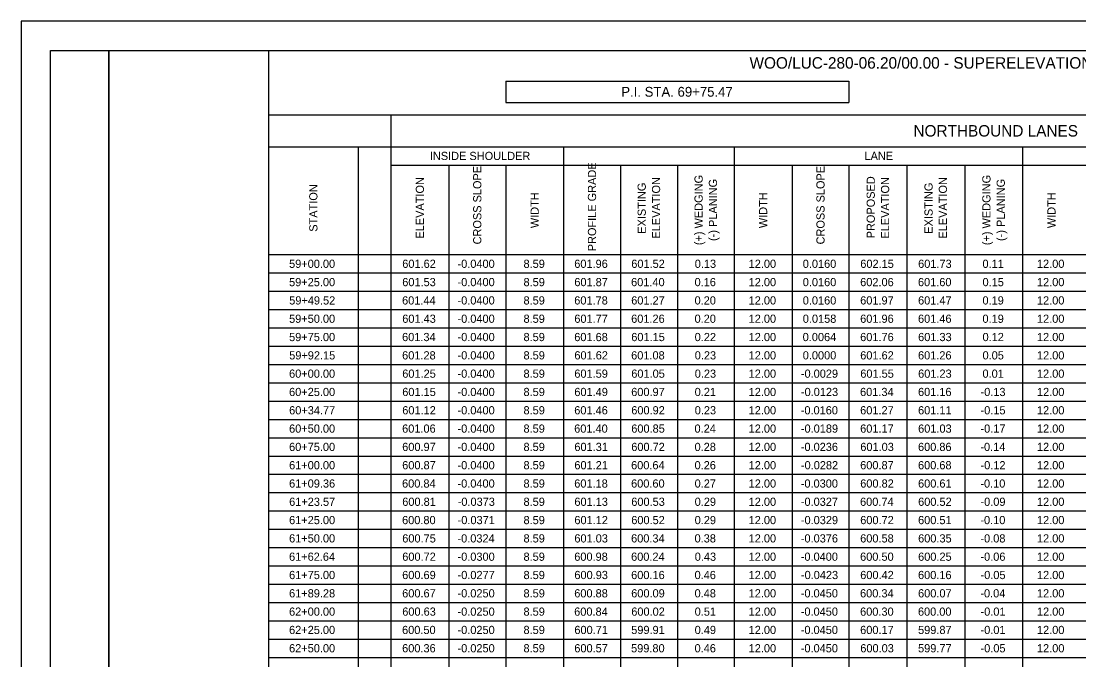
# Model space of a CAD drawing. Extents: x 0 to 34, y 0 to 22.
# Drawn here: x 0 to 18.07, y 11.08 to 22 of the extents above; entities that cross this region are included whole.
import ezdxf

# ---------------------------------------------------------------- set-up
doc = ezdxf.new("R2010")
doc.units = 0
for name, color, linetype in [('SH_Border', 7, 'Continuous'), ('SH_Cut_Line', 7, 'Continuous'), ('SH_Text', 7, 'Continuous')]:
    doc.layers.add(name, color=color, linetype=linetype)

msp = doc.modelspace()

# ---------------------------------------------------------------- linework, layer by layer
at = {"layer": 'SH_Border'}
for points in [[(0.5, 21.5), (1.5, 21.5), (1.5, 0.5), (0.5, 0.5)], [(1.5, 21.5), (33.5, 21.5), (33.5, 0.5), (1.5, 0.5)]]:
    msp.add_lwpolyline(points, close=True, dxfattribs=at)
at = {"layer": 'SH_Cut_Line'}
msp.add_lwpolyline([(0, 0), (34, 0), (34, 22), (0, 22)], close=True, dxfattribs=at)
at = {"layer": 'SH_Text'}
for p, q in [((4.225, 21.5), (29.277, 21.5)), ((4.225, 21.5), (4.225, 0.484)), ((8.277, 20.973), (14.14, 20.973)), ((8.277, 20.973), (8.277, 20.611)), ((14.14, 20.973), (14.14, 20.611)), ((8.277, 20.611), (14.14, 20.611)), ((4.225, 20.396), (29.277, 20.396)), ((6.317, 20.396), (6.317, 0.484)), ((4.225, 19.853), (29.277, 19.853)), ((5.757, 19.853), (5.757, 0.484)), ((9.265, 19.853), (9.265, 0.484)), ((12.18, 19.853), (12.18, 0.484)), ((17.105, 19.853), (17.105, 0.484)), ((6.317, 19.54), (26.954, 19.54)), ((7.305, 19.54), (7.305, 0.484)), ((8.277, 19.54), (8.277, 0.484)), ((10.237, 19.54), (10.237, 0.484)), ((11.209, 19.54), (11.209, 0.484)), ((13.169, 19.54), (13.169, 0.484)), ((14.14, 19.54), (14.14, 0.484)), ((15.129, 19.54), (15.129, 0.484)), ((16.117, 19.54), (16.117, 0.484)), ((4.225, 18.008), (29.277, 18.008)), ((4.225, 17.695), (29.277, 17.695)), ((4.225, 17.382), (29.277, 17.382)), ((4.225, 17.069), (29.277, 17.069)), ((4.225, 16.756), (29.277, 16.756)), ((4.225, 16.444), (29.277, 16.444)), ((4.225, 16.131), (29.277, 16.131)), ((4.225, 15.818), (29.277, 15.818)), ((4.225, 15.505), (29.277, 15.505)), ((4.225, 15.192), (29.277, 15.192)), ((4.225, 14.879), (29.277, 14.879)), ((4.225, 14.566), (29.277, 14.566)), ((4.225, 14.253), (29.277, 14.253)), ((4.225, 13.94), (29.277, 13.94)), ((4.225, 13.627), (29.277, 13.627)), ((4.225, 13.314), (29.277, 13.314)), ((4.225, 13.001), (29.277, 13.001)), ((4.225, 12.688), (29.277, 12.688)), ((4.225, 12.375), (29.277, 12.375)), ((4.225, 12.062), (29.277, 12.062)), ((4.225, 11.749), (29.277, 11.749)), ((4.225, 11.436), (29.277, 11.436)), ((4.225, 11.124), (29.277, 11.124))]:
    msp.add_line(p, q, dxfattribs=at)

# ---------------------------------------------------------------- texts
for s, height, p in [('WOO/LUC-280-06.20/00.00 - SUPERELEVATION TABLE', 0.196, (12.442, 21.188)), ('P.I. STA. 69+75.47', 0.168, (10.251, 20.708)), ('NORTHBOUND LANES', 0.196, (15.242, 20.027)), ('INSIDE SHOULDER', 0.14, (6.981, 19.626)), ('LANE', 0.14, (14.406, 19.626)), ('59+00.00', 0.14, (4.577, 17.782)), ('601.62', 0.14, (6.51, 17.782)), ('-0.0400', 0.14, (7.454, 17.782)), ('8.59', 0.14, (8.581, 17.782)), ('601.96', 0.14, (9.448, 17.782)), ('601.52', 0.14, (10.422, 17.782)), ('0.13', 0.14, (11.506, 17.782)), ('12.00', 0.14, (12.427, 17.782)), ('0.0160', 0.14, (13.351, 17.782)), ('602.15', 0.14, (14.334, 17.782)), ('601.73', 0.14, (15.322, 17.782)), ('0.11', 0.14, (16.421, 17.782)), ('12.00', 0.14, (17.352, 17.782)), ('59+25.00', 0.14, (4.577, 17.469)), ('601.53', 0.14, (6.51, 17.469)), ('-0.0400', 0.14, (7.454, 17.469)), ('8.59', 0.14, (8.581, 17.469)), ('601.87', 0.14, (9.449, 17.469)), ('601.40', 0.14, (10.419, 17.469)), ('0.16', 0.14, (11.503, 17.469)), ('12.00', 0.14, (12.427, 17.469)), ('0.0160', 0.14, (13.351, 17.469)), ('602.06', 0.14, (14.332, 17.469)), ('601.60', 0.14, (15.319, 17.469)), ('0.15', 0.14, (16.422, 17.469)), ('12.00', 0.14, (17.352, 17.469)), ('59+49.52', 0.14, (4.579, 17.156)), ('601.44', 0.14, (6.507, 17.156)), ('-0.0400', 0.14, (7.454, 17.156)), ('8.59', 0.14, (8.581, 17.156)), ('601.78', 0.14, (9.448, 17.156)), ('601.27', 0.14, (10.421, 17.156)), ('0.20', 0.14, (11.503, 17.156)), ('12.00', 0.14, (12.427, 17.156)), ('0.0160', 0.14, (13.351, 17.156)), ('601.97', 0.14, (14.332, 17.156)), ('601.47', 0.14, (15.321, 17.156)), ('0.19', 0.14, (16.421, 17.156)), ('12.00', 0.14, (17.352, 17.156)), ('59+50.00', 0.14, (4.577, 16.843)), ('601.43', 0.14, (6.51, 16.843)), ('-0.0400', 0.14, (7.454, 16.843)), ('8.59', 0.14, (8.581, 16.843)), ('601.77', 0.14, (9.449, 16.843)), ('601.26', 0.14, (10.42, 16.843)), ('0.20', 0.14, (11.503, 16.843)), ('12.00', 0.14, (12.427, 16.843)), ('0.0158', 0.14, (13.352, 16.843)), ('601.96', 0.14, (14.332, 16.843)), ('601.46', 0.14, (15.32, 16.843)), ('0.19', 0.14, (16.421, 16.843)), ('12.00', 0.14, (17.352, 16.843)), ('59+75.00', 0.14, (4.577, 16.53)), ('601.34', 0.14, (6.507, 16.53)), ('-0.0400', 0.14, (7.454, 16.53)), ('8.59', 0.14, (8.581, 16.53)), ('601.68', 0.14, (9.448, 16.53)), ('601.15', 0.14, (10.422, 16.53)), ('0.22', 0.14, (11.505, 16.53)), ('12.00', 0.14, (12.427, 16.53)), ('0.0064', 0.14, (13.35, 16.53)), ('601.76', 0.14, (14.332, 16.53)), ('601.33', 0.14, (15.322, 16.53)), ('0.12', 0.14, (16.422, 16.53)), ('12.00', 0.14, (17.352, 16.53)), ('59+92.15', 0.14, (4.579, 16.217)), ('601.28', 0.14, (6.508, 16.217)), ('-0.0400', 0.14, (7.454, 16.217)), ('8.59', 0.14, (8.581, 16.217)), ('601.62', 0.14, (9.45, 16.217)), ('601.08', 0.14, (10.42, 16.217)), ('0.23', 0.14, (11.506, 16.217)), ('12.00', 0.14, (12.427, 16.217)), ('0.0000', 0.14, (13.351, 16.217)), ('601.62', 0.14, (14.333, 16.217)), ('601.26', 0.14, (15.32, 16.217)), ('0.05', 0.14, (16.422, 16.217)), ('12.00', 0.14, (17.352, 16.217)), ('60+00.00', 0.14, (4.577, 15.904)), ('601.25', 0.14, (6.51, 15.904)), ('-0.0400', 0.14, (7.454, 15.904)), ('8.59', 0.14, (8.581, 15.904)), ('601.59', 0.14, (9.449, 15.904)), ('601.05', 0.14, (10.422, 15.904)), ('0.23', 0.14, (11.506, 15.904)), ('12.00', 0.14, (12.427, 15.904)), ('-0.0029', 0.14, (13.319, 15.904)), ('601.55', 0.14, (14.334, 15.904)), ('601.23', 0.14, (15.322, 15.904)), ('0.01', 0.14, (16.421, 15.904)), ('12.00', 0.14, (17.352, 15.904)), ('60+25.00', 0.14, (4.577, 15.591)), ('601.15', 0.14, (6.51, 15.591)), ('-0.0400', 0.14, (7.454, 15.591)), ('8.59', 0.14, (8.581, 15.591)), ('601.49', 0.14, (9.449, 15.591)), ('600.97', 0.14, (10.421, 15.591)), ('0.21', 0.14, (11.505, 15.591)), ('12.00', 0.14, (12.427, 15.591)), ('-0.0123', 0.14, (13.32, 15.591)), ('601.34', 0.14, (14.33, 15.591)), ('601.16', 0.14, (15.32, 15.591)), ('-0.13', 0.14, (16.388, 15.591)), ('12.00', 0.14, (17.352, 15.591)), ('60+34.77', 0.14, (4.578, 15.278)), ('601.12', 0.14, (6.51, 15.278)), ('-0.0400', 0.14, (7.454, 15.278)), ('8.59', 0.14, (8.581, 15.278)), ('601.46', 0.14, (9.448, 15.278)), ('600.92', 0.14, (10.422, 15.278)), ('0.23', 0.14, (11.506, 15.278)), ('12.00', 0.14, (12.427, 15.278)), ('-0.0160', 0.14, (13.317, 15.278)), ('601.27', 0.14, (14.332, 15.278)), ('601.11', 0.14, (15.321, 15.278)), ('-0.15', 0.14, (16.388, 15.278)), ('12.00', 0.14, (17.352, 15.278)), ('60+50.00', 0.14, (4.577, 14.965)), ('601.06', 0.14, (6.508, 14.965)), ('-0.0400', 0.14, (7.454, 14.965)), ('8.59', 0.14, (8.581, 14.965)), ('601.40', 0.14, (9.447, 14.965)), ('600.85', 0.14, (10.422, 14.965)), ('0.24', 0.14, (11.502, 14.965)), ('12.00', 0.14, (12.427, 14.965)), ('-0.0189', 0.14, (13.319, 14.965)), ('601.17', 0.14, (14.332, 14.965)), ('601.03', 0.14, (15.322, 14.965)), ('-0.17', 0.14, (16.387, 14.965)), ('12.00', 0.14, (17.352, 14.965)), ('60+75.00', 0.14, (4.577, 14.652)), ('600.97', 0.14, (6.509, 14.652)), ('-0.0400', 0.14, (7.454, 14.652)), ('8.59', 0.14, (8.581, 14.652)), ('601.31', 0.14, (9.45, 14.652)), ('600.72', 0.14, (10.422, 14.652)), ('0.28', 0.14, (11.503, 14.652)), ('12.00', 0.14, (12.427, 14.652)), ('-0.0236', 0.14, (13.318, 14.652)), ('601.03', 0.14, (14.334, 14.652)), ('600.86', 0.14, (15.32, 14.652)), ('-0.14', 0.14, (16.385, 14.652)), ('12.00', 0.14, (17.352, 14.652)), ('61+00.00', 0.14, (4.577, 14.339)), ('600.87', 0.14, (6.509, 14.339)), ('-0.0400', 0.14, (7.454, 14.339)), ('8.59', 0.14, (8.581, 14.339)), ('601.21', 0.14, (9.45, 14.339)), ('600.64', 0.14, (10.419, 14.339)), ('0.26', 0.14, (11.503, 14.339)), ('12.00', 0.14, (12.427, 14.339)), ('-0.0282', 0.14, (13.32, 14.339)), ('600.87', 0.14, (14.332, 14.339)), ('600.68', 0.14, (15.32, 14.339)), ('-0.12', 0.14, (16.388, 14.339)), ('12.00', 0.14, (17.352, 14.339)), ('61+09.36', 0.14, (4.577, 14.026)), ('600.84', 0.14, (6.507, 14.026)), ('-0.0400', 0.14, (7.454, 14.026)), ('8.59', 0.14, (8.581, 14.026)), ('601.18', 0.14, (9.448, 14.026)), ('600.60', 0.14, (10.419, 14.026)), ('0.27', 0.14, (11.504, 14.026)), ('12.00', 0.14, (12.427, 14.026)), ('-0.0300', 0.14, (13.317, 14.026)), ('600.82', 0.14, (14.333, 14.026)), ('600.61', 0.14, (15.321, 14.026)), ('-0.10', 0.14, (16.385, 14.026)), ('12.00', 0.14, (17.352, 14.026)), ('61+23.57', 0.14, (4.578, 13.714)), ('600.81', 0.14, (6.51, 13.714)), ('-0.0373', 0.14, (7.457, 13.714)), ('8.59', 0.14, (8.581, 13.714)), ('601.13', 0.14, (9.45, 13.714)), ('600.53', 0.14, (10.422, 13.714)), ('0.29', 0.14, (11.505, 13.714)), ('12.00', 0.14, (12.427, 13.714)), ('-0.0327', 0.14, (13.318, 13.714)), ('600.74', 0.14, (14.33, 13.714)), ('600.52', 0.14, (15.322, 13.714)), ('-0.09', 0.14, (16.387, 13.714)), ('12.00', 0.14, (17.352, 13.714)), ('61+25.00', 0.14, (4.577, 13.401)), ('600.80', 0.14, (6.507, 13.401)), ('-0.0371', 0.14, (7.456, 13.401)), ('8.59', 0.14, (8.581, 13.401)), ('601.12', 0.14, (9.45, 13.401)), ('600.52', 0.14, (10.422, 13.401)), ('0.29', 0.14, (11.505, 13.401)), ('12.00', 0.14, (12.427, 13.401)), ('-0.0329', 0.14, (13.319, 13.401)), ('600.72', 0.14, (14.333, 13.401)), ('600.51', 0.14, (15.321, 13.401)), ('-0.10', 0.14, (16.385, 13.401)), ('12.00', 0.14, (17.352, 13.401)), ('61+50.00', 0.14, (4.577, 13.088)), ('600.75', 0.14, (6.51, 13.088)), ('-0.0324', 0.14, (7.453, 13.088)), ('8.59', 0.14, (8.581, 13.088)), ('601.03', 0.14, (9.45, 13.088)), ('600.34', 0.14, (10.419, 13.088)), ('0.38', 0.14, (11.503, 13.088)), ('12.00', 0.14, (12.427, 13.088)), ('-0.0376', 0.14, (13.318, 13.088)), ('600.58', 0.14, (14.332, 13.088)), ('600.35', 0.14, (15.322, 13.088)), ('-0.08', 0.14, (16.386, 13.088)), ('12.00', 0.14, (17.352, 13.088)), ('61+62.64', 0.14, (4.576, 12.775)), ('600.72', 0.14, (6.51, 12.775)), ('-0.0300', 0.14, (7.454, 12.775)), ('8.59', 0.14, (8.581, 12.775)), ('600.98', 0.14, (9.448, 12.775)), ('600.24', 0.14, (10.419, 12.775)), ('0.43', 0.14, (11.506, 12.775)), ('12.00', 0.14, (12.427, 12.775)), ('-0.0400', 0.14, (13.317, 12.775)), ('600.50', 0.14, (14.331, 12.775)), ('600.25', 0.14, (15.322, 12.775)), ('-0.06', 0.14, (16.386, 12.775)), ('12.00', 0.14, (17.352, 12.775)), ('61+75.00', 0.14, (4.577, 12.462)), ('600.69', 0.14, (6.509, 12.462)), ('-0.0277', 0.14, (7.455, 12.462)), ('8.59', 0.14, (8.581, 12.462)), ('600.93', 0.14, (9.45, 12.462)), ('600.16', 0.14, (10.42, 12.462)), ('0.46', 0.14, (11.503, 12.462)), ('12.00', 0.14, (12.427, 12.462)), ('-0.0423', 0.14, (13.32, 12.462)), ('600.42', 0.14, (14.333, 12.462)), ('600.16', 0.14, (15.32, 12.462)), ('-0.05', 0.14, (16.388, 12.462)), ('12.00', 0.14, (17.352, 12.462)), ('61+89.28', 0.14, (4.577, 12.149)), ('600.67', 0.14, (6.509, 12.149)), ('-0.0250', 0.14, (7.454, 12.149)), ('8.59', 0.14, (8.581, 12.149)), ('600.88', 0.14, (9.448, 12.149)), ('600.09', 0.14, (10.421, 12.149)), ('0.48', 0.14, (11.503, 12.149)), ('12.00', 0.14, (12.427, 12.149)), ('-0.0450', 0.14, (13.317, 12.149)), ('600.34', 0.14, (14.33, 12.149)), ('600.07', 0.14, (15.321, 12.149)), ('-0.04', 0.14, (16.385, 12.149)), ('12.00', 0.14, (17.352, 12.149)), ('62+00.00', 0.14, (4.577, 11.836)), ('600.63', 0.14, (6.51, 11.836)), ('-0.0250', 0.14, (7.454, 11.836)), ('8.59', 0.14, (8.581, 11.836)), ('600.84', 0.14, (9.447, 11.836)), ('600.02', 0.14, (10.422, 11.836)), ('0.51', 0.14, (11.505, 11.836)), ('12.00', 0.14, (12.427, 11.836)), ('-0.0450', 0.14, (13.317, 11.836)), ('600.30', 0.14, (14.331, 11.836)), ('600.00', 0.14, (15.319, 11.836)), ('-0.01', 0.14, (16.388, 11.836)), ('12.00', 0.14, (17.352, 11.836)), ('62+25.00', 0.14, (4.577, 11.523)), ('600.50', 0.14, (6.507, 11.523)), ('-0.0250', 0.14, (7.454, 11.523)), ('8.59', 0.14, (8.581, 11.523)), ('600.71', 0.14, (9.45, 11.523)), ('599.91', 0.14, (10.421, 11.523)), ('0.49', 0.14, (11.505, 11.523)), ('12.00', 0.14, (12.427, 11.523)), ('-0.0450', 0.14, (13.317, 11.523)), ('600.17', 0.14, (14.332, 11.523)), ('599.87', 0.14, (15.321, 11.523)), ('-0.01', 0.14, (16.388, 11.523)), ('12.00', 0.14, (17.352, 11.523)), ('62+50.00', 0.14, (4.577, 11.21)), ('600.36', 0.14, (6.508, 11.21)), ('-0.0250', 0.14, (7.454, 11.21)), ('8.59', 0.14, (8.581, 11.21)), ('600.57', 0.14, (9.449, 11.21)), ('599.80', 0.14, (10.419, 11.21)), ('0.46', 0.14, (11.503, 11.21)), ('12.00', 0.14, (12.427, 11.21)), ('-0.0450', 0.14, (13.317, 11.21)), ('600.03', 0.14, (14.334, 11.21)), ('599.77', 0.14, (15.321, 11.21)), ('-0.05', 0.14, (16.388, 11.21)), ('12.00', 0.14, (17.352, 11.21))]:
    msp.add_text(s, height=height, dxfattribs=at).set_placement(p)
for s, p in [('CROSS SLOPE', (7.861, 18.183)), ('PROFILE GRADE', (9.821, 18.066)), ('CROSS SLOPE', (13.724, 18.183)), ('(+) WEDGING', (11.642, 18.17)), ('PROPOSED ', (14.582, 18.287)), ('(+) WEDGING', (16.558, 18.17)), ('STATION', (5.061, 18.4)), ('ELEVATION', (6.881, 18.283)), ('EXISTING ', (10.67, 18.365)), ('ELEVATION', (10.915, 18.283)), ('(-) PLANING', (11.887, 18.242)), ('ELEVATION', (14.827, 18.283)), ('EXISTING ', (15.57, 18.365)), ('ELEVATION', (15.815, 18.283)), ('(-) PLANING', (16.803, 18.242)), ('WIDTH', (8.841, 18.461)), ('WIDTH', (12.744, 18.461)), ('WIDTH', (17.669, 18.461))]:
    msp.add_text(s, height=0.14, rotation=90, dxfattribs=at).set_placement(p)

doc.saveas('drawing.dxf')
